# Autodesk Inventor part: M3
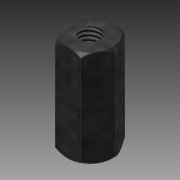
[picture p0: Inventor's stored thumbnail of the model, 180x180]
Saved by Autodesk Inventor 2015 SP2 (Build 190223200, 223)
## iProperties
Created: 2012-08
Part Number: M3
Material: Stahl
Document SubType Name: Modeling
Designer: rYan
Mass: 2.01551 g
Surface Area: 3.60689 cm^2
Volume: 0.256753 cm^3
Density: 7.85 g/cm^3
Appearance: Platte
Author: rYan
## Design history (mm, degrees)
derived "Abstandsbolzen Typ A.ipt"
feature "Volumenkörper1::Abstandsbolzen Typ A.ipt"
tag "Bezeichnung1"
node "Volumenkörper1"
other parameters: "SW" = 5.5, "L" = 12, "d2" = 0, "d16" = 45 deg
